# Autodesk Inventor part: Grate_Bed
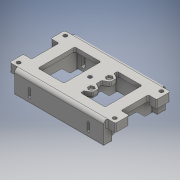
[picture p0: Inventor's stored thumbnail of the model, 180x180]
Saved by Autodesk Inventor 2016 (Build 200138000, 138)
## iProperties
Created: 2016-02
Part Number: Grate_Bed
Material: Generic
Document SubType Name: Modeling
Designer: John
Density: 1 g/cm^3
Appearance: Default
Author: John
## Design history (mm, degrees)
sketch "Sketch1"
  geometry: L1 (-65, 45)-(65, 45); L2 (65, 45)-(65, -45); L3 (65, -45)-(-65, -45); L4 (-65, -45)-(-65, 45); C1 r 2.75 at (0, 0); C2 r 2 at (15, -13.05); C3 r 2 at (15, 13.05); 3 further points
  constraints: 8 end point, 3 centre point, 2 midpoint, 2 parallel, 2 vertical alignment, 1 coincident, 1 equal radius, 1 horizontal, 1 horizontal alignment, 1 perpendicular
  dimensions: "d0" = 13.05 vertical distance of point (0, 0) C2.centre; "d1" = 13.05 vertical distance of C3.centre point (0, 0) (= d0); "d2" = 15 horizontal distance of point (0, 0) C2.centre; "d3" = 4 diameter of C3; "d4" = 5.5 diameter of C1; "d5" = 130 distance of L1.start L1.end; "d6" = 90 distance of L3.end L1.start
extrude "Extrusion1" new body sketch "Sketch1" distance "d7" = 8; taper "d8" = 0 deg
sketch "Sketch2"
  geometry: L1 (65, 45)-(-65, 45) reference; L2 (-65, 45)-(-65, -45) reference; L3 (-65, -45)-(65, -45) reference; L4 (65, -45)-(65, 45) reference; L5 (-65, -45)-(65, -45); L6 (65, -45)-(65, -33); L7 (65, -33)-(-65, -33); L8 (-65, -33)-(-65, -45); L9 (65, 45)-(-65, 45); L10 (-65, 45)-(-65, 33); L11 (-65, 33)-(65, 33); L12 (65, 33)-(65, 45); C1 r 2.75 at (0, 0) reference; C2 r 2 at (-15, 13.05) reference; C3 r 2 at (-15, -13.05) reference; 1 further point
  constraints: 16 end point, 4 parallel, 2 horizontal, 2 perpendicular, 2 point on line, 1 collinear
  dimensions: "d9" = 12 distance between parallel lines of L3 L7
extrude "Extrusion2" join sketch "Sketch2" distance "d10" = 25; taper "d11" = 0 deg
fillet "Fillet1" dims "d12" = 3
fillet "Fillet2" dims "d13" = 5
fillet "Fillet3" dims "d14" = 2
sketch "Sketch3"
  geometry: L1 (2, -28)-(128, -28) reference; L2 (130, 5)-(0, 5) reference; L3 (130, -3)-(0, -3) reference; L4 (0, -3)-(130, -3) reference; L5 (67.75, -3)-(62.25, -3) reference; L6 (82, -3)-(78, -3) reference; L7 (82, -3)-(78, -3) reference; L8 (22.137, -9)-(22.137, -19); L9 (20.512, -9)-(20.512, -19); L10 (23.762, -19)-(23.762, -9); L11 (107.863, -9)-(107.863, -19); L12 (106.238, -9)-(106.238, -19); L13 (109.487, -19)-(109.488, -9); L14 (130, 0)-(130, -26) reference; A1 r 1.625 centre (22.137, -9) between (23.762, -9) and (20.512, -9); A2 r 1.625 centre (22.137, -19) between (20.512, -19) and (23.762, -19); A3 r 1.625 centre (107.863, -9) between (109.488, -9) and (106.238, -9); A4 r 1.625 centre (107.863, -19) between (106.238, -19) and (109.487, -19); 3 further points
  constraints: 16 end point, 8 point on circle, 8 tangent, 4 centre point, 4 parallel, 2 midpoint, 1 equal radius, 1 horizontal alignment, 1 vertical
  dimensions: "d15" = 85.725 distance of point (107.863, -14) point (22.137, -14); "d16" = 130 distance of L3.start L3.end (derived); "d17" = 22.1375 distance between parallel lines of L14 L11 (= -0.5 x d15 + 0.5 x d16); "d18" = 1.625 radius of A1; "d19" = 10 distance of L8.start L8.end; "d20" = 6 distance from line of L4 L8.start
extrude "Extrusion3" cut sketch "Sketch3" stored distance "d21" = 25; taper "d22" = 0 deg
sketch "Sketch4"
  geometry: L1 (20.512, -19)-(20.512, -9) reference; L2 (23.762, -9)-(23.762, -19) reference; L3 (106.238, -19)-(106.238, -9) reference; L4 (109.488, -9)-(109.487, -19) reference; L5 (130, -26)-(0, -26) reference; L6 (130, 0)-(130, -26) reference; L7 (0, 0)-(130, 0) reference; L8 (0, 0)-(0, -26) reference; L9 (19.262, -7.34)-(22.137, -5.68); L10 (22.137, -5.68)-(25.012, -7.34); L11 (22.137, -22.32)-(19.262, -20.66); L12 (25.012, -20.66)-(22.137, -22.32); L13 (19.262, -20.66)-(19.262, -7.34); L14 (25.012, -20.66)-(25.012, -7.34); L15 (104.988, -7.34)-(104.988, -20.66); L16 (104.988, -20.66)-(107.863, -22.32); L17 (107.863, -22.32)-(110.738, -20.66); L18 (110.738, -20.66)-(110.738, -7.34); L19 (110.738, -7.34)-(107.863, -5.68); L20 (107.863, -5.68)-(104.988, -7.34); A1 r 1.625 centre (22.137, -19) between (20.512, -19) and (23.762, -19) reference; A2 r 1.625 centre (22.137, -9) between (23.762, -9) and (20.512, -9) reference; A3 r 1.625 centre (107.863, -19) between (106.238, -19) and (109.487, -19) reference; A4 r 1.625 centre (107.863, -9) between (109.488, -9) and (106.238, -9) reference; 3 further points
  constraints: 24 end point, 6 parallel, 5 equal length, 3 vertical alignment, 2 coincident, 2 horizontal alignment, 2 vertical, 8 other
  dimensions: "d23" = 5.75 distance between parallel lines of L13 L14; "d24" = 120 deg angle of L10 L9
  node "Projected Loop3"
workplane "Work Plane1"
workplane "Work Plane2"
workplane "Work Plane3"
workplane "Work Plane4"
extrude "Extrusion4" cut sketch "Sketch4" stored distance "d27" = 25; taper "d28" = 0 deg
extrude "Extrusion5" cut sketch "Sketch4" stored distance "d29" = 25; taper "d30" = 0 deg
sketch "Sketch5"
  geometry: L1 (-63, 35)-(-63, 43) reference; L2 (63, 35)-(-63, 35) reference; L3 (63, 43)-(63, 35) reference; L4 (-63, 43)-(63, 43) reference; L5 (-63, -35)-(63, -35) reference; L6 (-63, -43)-(-63, -35) reference; L7 (63, -43)-(-63, -43) reference; L8 (63, -35)-(63, -43) reference; L9 (57, 35)-(52, 35); L10 (52, 35)-(52, -35); L11 (52, -35)-(57, -35); L12 (57, -35)-(57, 35); L13 (-52, 35)-(-57, 35); L14 (-57, 35)-(-57, -35); L15 (-57, -35)-(-52, -35); L16 (-52, -35)-(-52, 35); L17 (-63, -35)-(63, -35) reference; L18 (65, 33)-(65, 45) reference; L19 (-65, 45)-(-65, 33) reference; 1 further point
  constraints: 16 end point, 4 parallel, 4 point on line, 2 horizontal, 2 perpendicular, 1 collinear
  dimensions: "d31" = 5 distance between parallel lines of L10 L12; "d32" = 8 distance between parallel lines of L18 L12; "d33" = 8 distance between parallel lines of L19 L14 (= d32)
extrude "Extrusion6" join sketch "Sketch5" stored distance "d34" = 25; taper "d35" = 0 deg
sketch "Sketch6"
  geometry: L1 (-63, -35)-(-57, -35) reference; L2 (-63, -43)-(-63, -35) reference; L3 (63, -43)-(-63, -43) reference; L4 (63, -35)-(63, -43) reference; L5 (57, -35)-(63, -35) reference; L6 (57, -35)-(57, 35) reference; L7 (63, 35)-(57, 35) reference; L8 (63, 43)-(63, 35) reference; L9 (-63, 43)-(63, 43) reference; L10 (-63, 35)-(-63, 43) reference; L11 (-57, 35)-(-63, 35) reference; L12 (-57, 35)-(-57, -35) reference; L13 (-52, -35)-(-52, 35) reference; L14 (52, 35)-(-52, 35) reference; L15 (52, 35)-(52, -35) reference; L16 (-52, -35)-(52, -35) reference; L17 (5, 35)-(-5, 35); L18 (-5, 35)-(-5, -35); L19 (-5, -35)-(5, -35); L20 (5, -35)-(5, 35); L21 (52, 35)-(-52, 35) reference; 2 further points
  constraints: 8 end point, 2 parallel, 2 point on line, 1 horizontal, 1 midpoint, 1 perpendicular, 1 vertical alignment
  dimensions: "d36" = 10 distance between parallel lines of L18 L20
extrude "Extrusion7" join sketch "Sketch6" stored distance "d37" = 25; taper "d38" = 0 deg
sketch "Sketch7"
  geometry: L1 (-65, 40)-(65, 40) reference; L2 (-65, 40)-(-65, -40) reference; L3 (65, -40)-(-65, -40) reference; L4 (65, -40)-(65, 40) reference; C1 r 2.75 at (0, 0) reference; C2 r 2 at (15, 13.05) reference; C3 r 2 at (15, -13.05) reference; 1 further point
extrude "Extrusion8" cut sketch "Sketch7" stored distance "d39" = 25; taper "d40" = 0 deg
sketch "Sketch8"
  geometry: L1 (-52, -35)-(-5, -35) reference; L2 (-52, -35)-(-52, 35) reference; L3 (-5, 35)-(-52, 35) reference; L4 (-5, 35)-(-5, -35) reference; L5 (-63, -35)-(-57, -35) reference; L6 (-63, -43)-(-63, -35) reference; L7 (63, -43)-(-63, -43) reference; L8 (63, -35)-(63, -43) reference; L9 (57, -35)-(63, -35) reference; L10 (57, -35)-(57, 35) reference; L11 (63, 35)-(57, 35) reference; L12 (63, 43)-(63, 35) reference; L13 (-63, 43)-(63, 43) reference; L14 (-63, 35)-(-63, 43) reference; L15 (-57, 35)-(-63, 35) reference; L16 (-57, 35)-(-57, -35) reference; L17 (5, -35)-(5, 35) reference; L18 (52, 35)-(5, 35) reference; L19 (52, 35)-(52, -35) reference; L20 (5, -35)-(52, -35) reference; L21 (4.35, -2.511)-(0, -5.023); L22 (0, -5.023)-(-4.35, -2.511); L23 (-4.35, -2.511)-(-4.35, 2.511); L24 (-4.35, 2.511)-(0, 5.023); L25 (0, 5.023)-(4.35, 2.511); L26 (4.35, 2.511)-(4.35, -2.511); L27 (0, -8.487)-(-7.35, -4.244); L28 (-7.35, -4.244)-(-7.35, 4.244); L29 (-7.35, 4.244)-(0, 8.487); L30 (0, 8.487)-(7.35, 4.244); L31 (7.35, 4.244)-(7.35, -4.244); L32 (7.35, -4.244)-(0, -8.487); C1 r 2.75 at (0, 0) reference; 3 further points
  constraints: 24 end point, 2 coincident, 2 vertical, 26 other
  dimensions: "d41" = 8.7 distance between parallel lines of L23 L26; "d42" = 3 distance between parallel lines of L26 L31
  node "Projected Loop8"
extrude "Extrusion9" join sketch "Sketch8" stored distance "d43" = 25; taper "d44" = 0 deg
extrude "Extrusion10" cut sketch "Sketch8" stored distance "d45" = 25; taper "d46" = 0 deg
sketch "Sketch9"
  geometry: L1 (-65, 40)-(65, 40) reference; L2 (-65, 40)-(-65, -40) reference; L3 (65, -40)-(-65, -40) reference; L4 (65, -40)-(65, 40) reference; C1 r 2.75 at (0, 0) reference; C2 r 2 at (15, 13.05) reference; C3 r 2 at (15, -13.05) reference; 1 further point
extrude "Extrusion11" join sketch "Sketch9" distance "d47" = 5; taper "d49" = 0 deg; dims "d48" = 8, "d50" = 0
fillet "Fillet4" dims "d51" = 0.5
sketch "Sketch10"
  geometry: L1 (-5, -5.6)-(-7.35, -4.244) reference; L2 (-7.35, -4.244)-(-7.35, 4.244) reference; L3 (-7.35, 4.244)-(-5, 5.6) reference; L4 (-5, 5.6)-(-5, 30) reference; L5 (-52, 30)-(-5, 30) reference; L6 (-52, 30)-(-52, -30) reference; L7 (-5, -30)-(-52, -30) reference; L8 (-5, -30)-(-5, -5.6) reference; L9 (7.35, -4.244)-(5, -5.6) reference; L10 (5, -5.6)-(5, -30) reference; L11 (52, -30)-(5, -30) reference; L12 (52, -30)-(52, 30) reference; L13 (5, 30)-(52, 30) reference; L14 (5, 30)-(5, 5.6) reference; L15 (5, 5.6)-(7.35, 4.244) reference; L16 (7.35, 4.244)-(7.35, -4.244) reference; L17 (-49, 27)-(-21, 27); L18 (-21, 27)-(-21, -27); L19 (-21, -27)-(-49, -27); L20 (-49, -27)-(-49, 27); L21 (49, 27)-(11, 27); L22 (11, 27)-(11, -27); L23 (11, -27)-(49, -27); L24 (49, -27)-(49, 27); C1 r 2.5 at (-15, 13.05) reference; C2 r 2.5 at (-15, -13.05) reference; 1 further point
  constraints: 16 end point, 4 parallel, 2 horizontal, 2 horizontal alignment, 2 perpendicular
  dimensions: "d52" = 3 distance between parallel lines of L5 L17; "d53" = 3 distance between parallel lines of L7 L19 (= d52); "d54" = 3 distance between parallel lines of L6 L20 (= d52); "d55" = 3 distance between parallel lines of L12 L24 (= d54); "d56" = 6 distance between parallel lines of L14 L22; "d57" = 6 distance from line of C1.centre L18
extrude "Extrusion12" cut sketch "Sketch10" stored distance "d58" = 5; taper "d59" = 0 deg
sketch "Sketch11"
  geometry: L1 (0, 70)-(0, 0) reference; L2 (-22, 68)-(-2, 68) reference; L3 (-25, 5)-(-25, 65) reference; L4 (-2, 2)-(-22, 2) reference; L5 (0, 12)-(-12, 24); L6 (-12, 24)-(-12, 46); L7 (-12, 46)-(0, 58); A1 r 2 centre (-2, 0) between (0, 0) and (-2, 2) reference; A2 r 2 centre (-2, 70) between (-2, 68) and (0, 70) reference; A3 r 3 centre (-22, 65) between (-22, 68) and (-25, 65) reference; A4 r 3 centre (-22, 5) between (-25, 5) and (-22, 2) reference; 3 further points
  constraints: 6 end point, 2 midpoint, 2 point on line, 1 horizontal alignment, 1 vertical
  dimensions: "d60" = 45 deg angle of L1 L5; "d61" = 45 deg angle of L1 L7 (= d60); "d62" = 12 distance between parallel lines of L1 L6; "d63" = 46 distance of L7.end L5.start
extrude "Extrusion13" cut sketch "Sketch11" stored distance "d64" = 5; taper "d65" = 0 deg
fillet "Fillet5" dims "d66" = 5
fillet "Fillet6" dims "d67" = 1
sketch "Sketch12"
  geometry: L1 (-6, -5.023)-(-6, -30) reference; L2 (-6, -5.023)-(-7.35, -4.244) reference; L3 (-7.35, -4.244)-(-7.35, 4.244) reference; L4 (-7.35, 4.244)-(-6, 5.023) reference; L5 (-6, 30)-(-6, 5.023) reference; L6 (-51, 30)-(-6, 30) reference; L7 (-51, -30)-(-51, 30) reference; L8 (-6, -30)-(-51, -30) reference; L9 (-49, -27)-(-49, 27) reference; L10 (-49, 27)-(-21, 27) reference; L11 (-21, 27)-(-21, -27) reference; L12 (-21, -27)-(-49, -27) reference; L13 (-21, 27)-(-13, 27); L14 (-13, 27)-(-13, 22); L15 (-13, 22)-(-21, 17.381); L16 (-21, -27)-(-13, -27); L17 (-13, -27)-(-13, -22); L18 (-13, -22)-(-21, -17.381); L19 (-21, -8.619)-(-13, -4); L20 (-13, -4)-(-13, 4); L21 (-13, 4)-(-21, 8.619); C1 r 2.5 at (-15, 13.05) reference; C2 r 2.5 at (-15, -13.05) reference; 3 further points
  constraints: 18 end point, 6 point on line, 2 collinear, 2 midpoint, 2 perpendicular, 1 horizontal, 1 horizontal alignment, 1 vertical alignment
  dimensions: "d68" = 8 distance of L11.end L16.end; "d69" = 60 deg angle of L11 L18; "d70" = 5 distance of L16.end L17.end; "d71" = 60 deg angle of L11 L15 (= d69); "d72" = 8 distance between parallel lines of L11 L20; "d73" = 60 deg angle of L11 L19 (= d69); "d74" = 60 deg angle of L11 L21 (= d71); "d75" = 8 distance of L19.end L20.end
extrude "Extrusion14" cut sketch "Sketch12" stored distance "d76" = 5; taper "d77" = 0 deg
fillet "Fillet7" dims "d78" = 2
sketch "Sketch13"
  geometry: L1 (21, -16.226)-(21, -9.774) reference; L2 (20, -8.041)-(14, -4.577) reference; L3 (13, -2.845)-(13, 2.845) reference; L4 (14, 4.577)-(20, 8.041) reference; L5 (21, 9.774)-(21, 16.226) reference; L6 (20, 17.959)-(14, 21.423) reference; L7 (13, 23.155)-(13, 25) reference; L8 (15, 27)-(49, 27) reference; L9 (49, 27)-(49, -27) reference; L10 (49, -27)-(15, -27) reference; L11 (13, -25)-(13, -23.155) reference; L12 (14, -21.423)-(20, -17.959) reference; L13 (-11, 27)-(-11, -27) reference; L14 (-11, -27)-(-49, -27) reference; L15 (-49, -27)-(-49, 27) reference; L16 (-49, 27)-(-11, 27) reference; L17 (-65, 40)-(65, 40) reference; L18 (-65, 40)-(-65, -40) reference; L19 (65, -40)-(-65, -40) reference; L20 (65, -40)-(65, 40) reference; L21 (65, 40)-(77, 40); L22 (77, 40)-(77, 20); L23 (77, 20)-(65, 20); L24 (65, 20)-(65, 40); L25 (65, -40)-(77, -40); L26 (77, -40)-(77, -20); L27 (77, -20)-(65, -20); L28 (65, -20)-(65, -40); L29 (-65, 40)-(-77, 40); L30 (-77, 40)-(-77, 20); L31 (-77, 20)-(-65, 20); L32 (-65, 20)-(-65, 40); L33 (-65, -40)-(-77, -40); L34 (-77, -40)-(-77, -20); L35 (-77, -20)-(-65, -20); L36 (-65, -20)-(-65, -40); C1 r 2.5 at (15, -13.05) reference; C2 r 2.75 at (0, 0) reference; C3 r 2.5 at (15, 13.05) reference; C4 r 2.75 at (-70, 34); C5 r 2.75 at (-70, -34); C6 r 2.75 at (70, 34); C7 r 2.75 at (70, -34); A1 r 2 centre (19, -16.226) between (20, -17.959) and (21, -16.226) reference; A2 r 2 centre (19, -9.774) between (21, -9.774) and (20, -8.041) reference; A3 r 2 centre (15, -2.845) between (13, -2.845) and (14, -4.577) reference; A4 r 2 centre (15, 2.845) between (14, 4.577) and (13, 2.845) reference; A5 r 2 centre (19, 9.774) between (20, 8.041) and (21, 9.774) reference; A6 r 2 centre (19, 16.226) between (21, 16.226) and (20, 17.959) reference; A7 r 2 centre (15, 23.155) between (13, 23.155) and (14, 21.423) reference; A8 r 2 centre (15, 25) between (15, 27) and (13, 25) reference; A9 r 2 centre (15, -25) between (13, -25) and (15, -27) reference; A10 r 2 centre (15, -23.155) between (14, -21.423) and (13, -23.155) reference; 1 further point
  constraints: 32 end point, 8 parallel, 4 centre point, 4 collinear, 4 horizontal, 4 perpendicular, 3 equal radius, 2 horizontal alignment, 2 point on line, 2 vertical alignment
  dimensions: "d79" = 20 distance of L29.end L30.end; "d80" = 12 distance of L17.start L29.end; "d81" = 5.5 diameter of C7; "d82" = 5 distance from line of L24 C6.centre; "d83" = 5 distance from line of L18 C4.centre (= d82); "d84" = 6 distance from line of L29 C4.centre; "d85" = 6 distance from line of L33 C5.centre (= d84)
extrude "Extrusion15" join sketch "Sketch13" distance "d86" = 12; taper "d87" = 0 deg
fillet "Fillet8" dims "d88" = 2
sketch "Sketch14"
  geometry: L1 (75, 40)-(67, 40) reference; L2 (67, 40)-(-67, 40) reference; L3 (-67, 40)-(-75, 40) reference; L4 (-77, 38)-(-77, 22) reference; L5 (-75, 20)-(-67, 20) reference; L6 (-65, 18)-(-65, -18) reference; L7 (-67, -20)-(-75, -20) reference; L8 (-77, -22)-(-77, -38) reference; L9 (-75, -40)-(-67, -40) reference; L10 (-67, -40)-(67, -40) reference; L11 (67, -40)-(75, -40) reference; L12 (77, -38)-(77, -22) reference; L13 (75, -20)-(67, -20) reference; L14 (65, -18)-(65, 18) reference; L15 (67, 20)-(75, 20) reference; L16 (77, 22)-(77, 38) reference; L17 (-11, 27)-(-11, -27) reference; L18 (-11, -27)-(-49, -27) reference; L19 (-49, -27)-(-49, 27) reference; L20 (-49, 27)-(-11, 27) reference; L21 (21, -16.226)-(21, -9.774) reference; L22 (20, -8.041)-(14, -4.577) reference; L23 (13, -2.845)-(13, 2.845) reference; L24 (14, 4.577)-(20, 8.041) reference; L25 (21, 9.774)-(21, 16.226) reference; L26 (20, 17.959)-(14, 21.423) reference; L27 (13, 23.155)-(13, 25) reference; L28 (15, 27)-(49, 27) reference; L29 (49, 27)-(49, -27) reference; L30 (49, -27)-(15, -27) reference; L31 (13, -25)-(13, -23.155) reference; L32 (14, -21.423)-(20, -17.959) reference; C1 r 2.5 at (15, 13.05) reference; C2 r 2.75 at (0, 0) reference; C3 r 2.5 at (15, -13.05) reference; C4 r 2.75 at (70, 34) reference; C5 r 2.75 at (-70, -34) reference; C6 r 2.75 at (70, -34) reference; C7 r 2.75 at (-70, 34) reference; C8 r 2 at (15, -13.05) reference; C9 r 2 at (15, 13.05) reference; A1 r 2 centre (75, 38) between (77, 38) and (75, 40) reference; A2 r 2 centre (-75, 38) between (-75, 40) and (-77, 38) reference; A3 r 2 centre (-75, 22) between (-77, 22) and (-75, 20) reference; A4 r 2 centre (-67, 18) between (-65, 18) and (-67, 20) reference; A5 r 2 centre (-67, -18) between (-67, -20) and (-65, -18) reference; A6 r 2 centre (-75, -22) between (-75, -20) and (-77, -22) reference; A7 r 2 centre (-75, -38) between (-77, -38) and (-75, -40) reference; A8 r 2 centre (75, -38) between (75, -40) and (77, -38) reference; A9 r 2 centre (75, -22) between (77, -22) and (75, -20) reference; A10 r 2 centre (67, -18) between (65, -18) and (67, -20) reference; A11 r 2 centre (67, 18) between (67, 20) and (65, 18) reference; A12 r 2 centre (75, 22) between (75, 20) and (77, 22) reference; A13 r 2 centre (19, -16.226) between (20, -17.959) and (21, -16.226) reference; A14 r 2 centre (19, -9.774) between (21, -9.774) and (20, -8.041) reference; A15 r 2 centre (15, -2.845) between (13, -2.845) and (14, -4.577) reference; A16 r 2 centre (15, 2.845) between (14, 4.577) and (13, 2.845) reference; A17 r 2 centre (19, 9.774) between (20, 8.041) and (21, 9.774) reference; A18 r 2 centre (19, 16.226) between (21, 16.226) and (20, 17.959) reference; A19 r 2 centre (15, 23.155) between (13, 23.155) and (14, 21.423) reference; A20 r 2 centre (15, 25) between (15, 27) and (13, 25) reference; A21 r 2 centre (15, -25) between (13, -25) and (15, -27) reference; A22 r 2 centre (15, -23.155) between (14, -21.423) and (13, -23.155) reference; 1 further point
  node "Projected Loop15"
extrude "Extrusion16" cut sketch "Sketch14" stored distance "d89" = 12; taper "d90" = 0 deg
extrude "Extrusion17" cut sketch "Sketch14" stored distance "d91" = 12; taper "d92" = 0 deg
sketch "Sketch15"
  geometry: L1 (75, 40)-(67, 40) reference; L2 (67, 40)-(-67, 40) reference; L3 (-67, 40)-(-75, 40) reference; L4 (-77, 38)-(-77, 22) reference; L5 (-75, 20)-(-67, 20) reference; L6 (-65, 18)-(-65, -18) reference; L7 (-67, -20)-(-75, -20) reference; L8 (-77, -22)-(-77, -38) reference; L9 (-75, -40)-(-67, -40) reference; L10 (-67, -40)-(67, -40) reference; L11 (67, -40)-(75, -40) reference; L12 (77, -38)-(77, -22) reference; L13 (75, -20)-(67, -20) reference; L14 (65, -18)-(65, 18) reference; L15 (67, 20)-(75, 20) reference; L16 (77, 22)-(77, 38) reference; L17 (-11, 27)-(-11, -27) reference; L18 (-11, -27)-(-49, -27) reference; L19 (-49, -27)-(-49, 27) reference; L20 (-49, 27)-(-11, 27) reference; L21 (21, -16.226)-(21, -9.774) reference; L22 (20, -8.041)-(14, -4.577) reference; L23 (13, -2.845)-(13, 2.845) reference; L24 (14, 4.577)-(20, 8.041) reference; L25 (21, 9.774)-(21, 16.226) reference; L26 (20, 17.959)-(14, 21.423) reference; L27 (13, 23.155)-(13, 25) reference; L28 (15, 27)-(49, 27) reference; L29 (49, 27)-(49, -27) reference; L30 (49, -27)-(15, -27) reference; L31 (13, -25)-(13, -23.155) reference; L32 (14, -21.423)-(20, -17.959) reference; L33 (11.15, -10.827)-(15, -8.604); L34 (15, -8.604)-(18.85, -10.827); L35 (18.85, -10.827)-(18.85, -15.273); L36 (18.85, -15.273)-(15, -17.496); L37 (15, -17.496)-(11.15, -15.273); L38 (11.15, -15.273)-(11.15, -10.827); L39 (11.15, 15.273)-(15, 17.496); L40 (15, 17.496)-(18.85, 15.273); L41 (18.85, 15.273)-(18.85, 10.827); L42 (18.85, 10.827)-(15, 8.604); L43 (15, 8.604)-(11.15, 10.827); L44 (11.15, 10.827)-(11.15, 15.273); C1 r 2 at (15, 13.05) reference; C2 r 2 at (15, -13.05) reference; C3 r 2.75 at (0, 0) reference; C4 r 2.75 at (70, 34) reference; C5 r 2.75 at (-70, -34) reference; C6 r 2.75 at (70, -34) reference; C7 r 2.75 at (-70, 34) reference; A1 r 2 centre (75, 38) between (77, 38) and (75, 40) reference; A2 r 2 centre (-75, 38) between (-75, 40) and (-77, 38) reference; A3 r 2 centre (-75, 22) between (-77, 22) and (-75, 20) reference; A4 r 2 centre (-67, 18) between (-65, 18) and (-67, 20) reference; A5 r 2 centre (-67, -18) between (-67, -20) and (-65, -18) reference; A6 r 2 centre (-75, -22) between (-75, -20) and (-77, -22) reference; A7 r 2 centre (-75, -38) between (-77, -38) and (-75, -40) reference; A8 r 2 centre (75, -38) between (75, -40) and (77, -38) reference; A9 r 2 centre (75, -22) between (77, -22) and (75, -20) reference; A10 r 2 centre (67, -18) between (65, -18) and (67, -20) reference; A11 r 2 centre (67, 18) between (67, 20) and (65, 18) reference; A12 r 2 centre (75, 22) between (75, 20) and (77, 22) reference; A13 r 2 centre (19, -16.226) between (20, -17.959) and (21, -16.226) reference; A14 r 2 centre (19, -9.774) between (21, -9.774) and (20, -8.041) reference; A15 r 2 centre (15, -2.845) between (13, -2.845) and (14, -4.577) reference; A16 r 2 centre (15, 2.845) between (14, 4.577) and (13, 2.845) reference; A17 r 2 centre (19, 9.774) between (20, 8.041) and (21, 9.774) reference; A18 r 2 centre (19, 16.226) between (21, 16.226) and (20, 17.959) reference; A19 r 2 centre (15, 23.155) between (13, 23.155) and (14, 21.423) reference; A20 r 2 centre (15, 25) between (15, 27) and (13, 25) reference; A21 r 2 centre (15, -25) between (13, -25) and (15, -27) reference; A22 r 2 centre (15, -23.155) between (14, -21.423) and (13, -23.155) reference; 3 further points
  constraints: 24 end point, 2 coincident, 2 vertical, 1 collinear, 26 other
  dimensions: "d93" = 7.7 distance between parallel lines of L41 L44
extrude "Extrusion18" cut sketch "Sketch15" distance "d94" = 3; taper "d95" = 0 deg
chamfer "Chamfer1" distance "d96" = 2; stored, may be unused: second distance "d97" = 2, angle "d98" = 45 deg
fillet "Fillet9" dims "d99" = 2
sketch "Sketch16"
  geometry: L1 (77, 22)-(77, 38) reference; L2 (75, 40)-(67, 40) reference; L3 (65, 33)-(65, 42) reference; L4 (63, 33)-(65, 33) reference; L5 (65, 31)-(65, 22) reference; L6 (67, 20)-(75, 20) reference; L7 (77, -38)-(77, -22) reference; L8 (75, -20)-(67, -20) reference; L9 (65, -22)-(65, -31) reference; L10 (65, -33)-(63, -33) reference; L11 (65, -42)-(65, -33) reference; L12 (67, -40)-(75, -40) reference; L13 (-77, 38)-(-77, 22) reference; L14 (-75, 20)-(-67, 20) reference; L15 (-65, 22)-(-65, 31) reference; L16 (-65, 33)-(-63, 33) reference; L17 (-65, 42)-(-65, 33) reference; L18 (-67, 40)-(-75, 40) reference; L19 (-67, -20)-(-75, -20) reference; L20 (-77, -22)-(-77, -38) reference; L21 (-75, -40)-(-67, -40) reference; L22 (-65, -33)-(-65, -42) reference; L23 (-63, -33)-(-65, -33) reference; L24 (-65, -31)-(-65, -22) reference; L25 (-70, 39.023)-(-65.65, 36.511); L26 (-65.65, 36.511)-(-65.65, 31.489); L27 (-65.65, 31.489)-(-70, 28.977); L28 (-70, 28.977)-(-74.35, 31.489); L29 (-74.35, 31.489)-(-74.35, 36.511); L30 (-74.35, 36.511)-(-70, 39.023); L31 (-70, -39.023)-(-74.35, -36.511); L32 (-74.35, -36.511)-(-74.35, -31.489); L33 (-74.35, -31.489)-(-70, -28.977); L34 (-70, -28.977)-(-65.65, -31.489); L35 (-65.65, -31.489)-(-65.65, -36.511); L36 (-65.65, -36.511)-(-70, -39.023); L37 (70, 39.023)-(74.35, 36.511); L38 (74.35, 36.511)-(74.35, 31.489); L39 (74.35, 31.489)-(70, 28.977); L40 (70, 28.977)-(65.65, 31.489); L41 (65.65, 31.489)-(65.65, 36.511); L42 (65.65, 36.511)-(70, 39.023); L43 (70, -39.023)-(65.65, -36.511); L44 (65.65, -36.511)-(65.65, -31.489); L45 (65.65, -31.489)-(70, -28.977); L46 (70, -28.977)-(74.35, -31.489); L47 (74.35, -31.489)-(74.35, -36.511); L48 (74.35, -36.511)-(70, -39.023); C1 r 2.75 at (70, 34) reference; C2 r 2.75 at (70, -34) reference; C3 r 2.75 at (-70, 34) reference; C4 r 2.75 at (-70, -34) reference; A1 r 2 centre (75, 22) between (75, 20) and (77, 22) reference; A2 r 2 centre (75, 38) between (77, 38) and (75, 40) reference; A3 r 2 centre (67, 42) between (65, 42) and (67, 40) reference; A4 r 2 centre (63, 31) between (65, 31) and (63, 33) reference; A5 r 2 centre (67, 22) between (65, 22) and (67, 20) reference; A6 r 2 centre (75, -38) between (75, -40) and (77, -38) reference; A7 r 2 centre (75, -22) between (77, -22) and (75, -20) reference; A8 r 2 centre (67, -22) between (67, -20) and (65, -22) reference; A9 r 2 centre (63, -31) between (63, -33) and (65, -31) reference; A10 r 2 centre (67, -42) between (67, -40) and (65, -42) reference; A11 r 2 centre (-75, 38) between (-75, 40) and (-77, 38) reference; A12 r 2 centre (-75, 22) between (-77, 22) and (-75, 20) reference; A13 r 2 centre (-67, 22) between (-67, 20) and (-65, 22) reference; A14 r 2 centre (-63, 31) between (-63, 33) and (-65, 31) reference; A15 r 2 centre (-67, 42) between (-67, 40) and (-65, 42) reference; A16 r 2 centre (-67, -22) between (-65, -22) and (-67, -20) reference; A17 r 2 centre (-75, -22) between (-75, -20) and (-77, -22) reference; A18 r 2 centre (-75, -38) between (-77, -38) and (-75, -40) reference; A19 r 2 centre (-67, -42) between (-65, -42) and (-67, -40) reference; A20 r 2 centre (-63, -31) between (-65, -31) and (-63, -33) reference; 5 further points
  constraints: 48 end point, 4 coincident, 4 vertical, 3 equal length, 52 other
  dimensions: "d100" = 8.7 distance between parallel lines of L35 L32
extrude "Extrusion19" cut sketch "Sketch16" distance "d101" = 6; taper "d102" = 0 deg
fillet "Fillet10" dims "d103" = 2
chamfer "Chamfer2" distance "d104" = 2; stored, may be unused: second distance "d105" = 2, angle "d106" = 45 deg
chamfer "Chamfer3" distance "d107" = 2; stored, may be unused: second distance "d108" = 2, angle "d109" = 45 deg
body "Solid1"
node "Projected Loop1"
node "Projected Loop2"
node "Projected Loop4"
node "Projected Loop5"
node "Projected Loop6"
node "Projected Loop7"
node "Projected Loop9"
node "Projected Loop10"
node "Projected Loop11" dims "d13" = 5, "d55" = 3 (= d54), "d74" = 60 deg (= d71)
node "Projected Loop12"
node "Projected Loop13"
node "Projected Loop14"
node "Projected Loop16"
node "Projected Loop17"
node "Projected Loop18"
node "Projected Loop19"
node "Projected Loop20"
other parameters: "d25" = -5, "d26" = -5
